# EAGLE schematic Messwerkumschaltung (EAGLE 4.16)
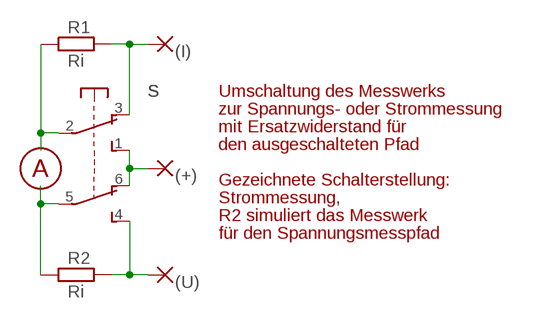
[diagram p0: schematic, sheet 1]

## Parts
(+)  WIREPAD3,81/1,1  [3,81/1,1]
(I)  WIREPAD3,81/1,1  [3,81/1,1]
(U)  WIREPAD3,81/1,1  [3,81/1,1]
R1  Ri  R-EU_0207/10  [0207/10]
R2  Ri  R-EU_0207/10  [0207/10]
S  9450-2  [9450-2]

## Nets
N$31: (U).1(P) R2.2 S.4(2:S)
N$43: (+).1(P) S.1(1:S) S.6(2:O)
N$49: (I).1(P) R1.2 S.3(1:O)
N$50: R1.1 S.2(1:P)
N$51: R2.1 S.5(2:P)

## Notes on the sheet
- Umschaltung des Messwerks
- zur Spannungs- oder Strommessung
- mit Ersatzwiderstand für
- den ausgeschalteten Pfad
- A
- Gezeichnete Schalterstellung:
- Strommessung,
- R2 simuliert das Messwerk
- für den Spannungsmesspfad

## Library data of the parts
(+) (I) (U) = wirepad:WIREPAD: Wire PAD connect wire on PCB
R1 R2 = rcl:R-EU_: RESISTOR, European symbol
S = switch-misc:9450-2: MARQUARDT SWITCH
